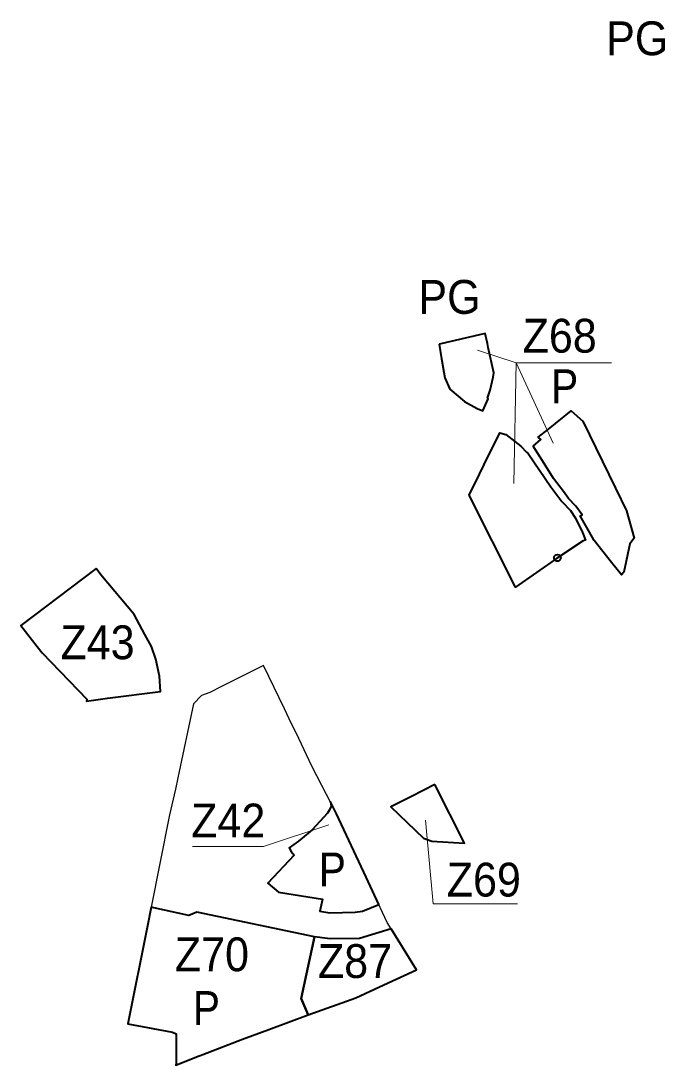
# Model space of a CAD drawing. Extents: x -650276 to -642489, y -1074425 to -1066658.
# Drawn here: x -647280 to -646824, y -1071533 to -1070793 of the extents above; entities that cross this region are included whole.
import ezdxf

# ---------------------------------------------------------------- set-up
doc = ezdxf.new("R2010")
doc.units = 0
doc.header["$LTSCALE"] = 9.6
doc.header["$PDMODE"] = 32
doc.header["$PDSIZE"] = 4.8
for name, color, linetype, lineweight in [('42', 7, 'Continuous', 25), ('44', 7, 'Continuous', 40), ('45', 7, 'Continuous', 40), ('46', 7, 'Continuous', 13), ('60', 7, 'Continuous', 35)]:
    doc.layers.add(name, color=color, linetype=linetype, lineweight=lineweight)

msp = doc.modelspace()

# ---------------------------------------------------------------- linework, layer by layer
at = {"layer": '42'}
msp.add_lwpolyline([(-647187.85, -1071421.58), (-647190.4, -1071434.75), (-647204.42, -1071504.1), (-647172.74, -1071510.15), (-647170.01, -1071511.22), (-647170.18, -1071532.22), (-647170.23, -1071533.44), (-647155.58, -1071527.62), (-647151.28, -1071525.99), (-647123.17, -1071515.01), (-647104.47, -1071508.08), (-647076.46, -1071497.69), (-647042.78, -1071485.76), (-647022.81, -1071476.61), (-646999.77, -1071465.81), (-647017.7, -1071436.79), (-647020.52, -1071432.42), (-647030.23, -1071411.53), (-647035.47, -1071400.31), (-647056.48, -1071355.32), (-647073.98, -1071321.53), (-647083.22, -1071302), (-647090, -1071287.89), (-647093.39, -1071280.83), (-647108.16, -1071250.08), (-647130.76, -1071261.49), (-647137.84, -1071265.06), (-647146.3, -1071269.33), (-647152.09, -1071271.47), (-647157.83, -1071277.35), (-647168.91, -1071329.88), (-647170.63, -1071337.91), (-647174.73, -1071356.1), (-647181.75, -1071390.51)], close=True, dxfattribs=at)
at = {"layer": '44'}
msp.add_line((-647081.488, -1071486.251), (-647076.46, -1071497.69), dxfattribs=at)
for points in [[(-647017.7, -1071436.79), (-647040.089, -1071443.76), (-647060.812, -1071444.006), (-647072.11, -1071442.6), (-647081.488, -1071486.251)], [(-647076.46, -1071497.69), (-647042.78, -1071485.76), (-647022.81, -1071476.61), (-646999.77, -1071465.81), (-647017.7, -1071436.79)]]:
    msp.add_lwpolyline(points, dxfattribs=at)
at = {"layer": '45'}
for points in [[(-646983.66, -1071022.3), (-646982.08, -1071032.76), (-646979.75, -1071046.19), (-646976.03, -1071054.29), (-646965.69, -1071063.05), (-646956.66, -1071067.91), (-646952.75, -1071069.62), (-646948.83, -1071061.12), (-646949.48, -1071060.79), (-646947.41, -1071054.95), (-646945.38, -1071045.82), (-646944.88, -1071042.78), (-646948.89, -1071024.84), (-646949.39, -1071021.83), (-646951.06, -1071014.78), (-646955.09, -1071015.67), (-646982.41, -1071022.23)], [(-646983.66, -1071022.3), (-646982.08, -1071032.76), (-646979.75, -1071046.19), (-646976.03, -1071054.29), (-646965.69, -1071063.05), (-646956.66, -1071067.91), (-646952.75, -1071069.62), (-646948.83, -1071061.12), (-646949.48, -1071060.79), (-646947.41, -1071054.95), (-646945.38, -1071045.82), (-646944.88, -1071042.78), (-646948.89, -1071024.84), (-646949.39, -1071021.83), (-646951.06, -1071014.78), (-646955.09, -1071015.67), (-646982.41, -1071022.23)], [(-646917.04, -1071094.75), (-646911.58, -1071089.9), (-646913.49, -1071088.22), (-646906.17, -1071082.72), (-646890.12, -1071069.67), (-646881.89, -1071077.03), (-646858.769, -1071124.46), (-646850.93, -1071140.54), (-646845.39, -1071159.98), (-646848.58, -1071163.95), (-646852.86, -1071183.98), (-646854.49, -1071185.87), (-646861.58, -1071177.05), (-646873.89, -1071161.58), (-646877.226, -1071155.611), (-646883.63, -1071144.15), (-646882.37, -1071143.39), (-646886.78, -1071137.25), (-646892.11, -1071131.81), (-646895.56, -1071126.84), (-646902.62, -1071117.58), (-646910.53, -1071105.18)], [(-646917.04, -1071094.75), (-646911.58, -1071089.9), (-646913.49, -1071088.22), (-646906.17, -1071082.72), (-646890.12, -1071069.67), (-646881.89, -1071077.03), (-646858.769, -1071124.46), (-646850.93, -1071140.54), (-646845.39, -1071159.98), (-646848.58, -1071163.95), (-646852.86, -1071183.98), (-646854.49, -1071185.87), (-646861.58, -1071177.05), (-646873.89, -1071161.58), (-646877.226, -1071155.611), (-646883.63, -1071144.15), (-646882.37, -1071143.39), (-646886.78, -1071137.25), (-646892.11, -1071131.81), (-646895.56, -1071126.84), (-646902.62, -1071117.58), (-646910.53, -1071105.18)], [(-646921.668, -1071098.861), (-646920.54, -1071099.98), (-646904.64, -1071123.54), (-646896.62, -1071133.93), (-646890.59, -1071140.39), (-646887.07, -1071145.66), (-646881.97, -1071155.84), (-646879.91, -1071161.24), (-646881.68, -1071161.83), (-646899.85, -1071173.89), (-646929.64, -1071194.58), (-646962.471, -1071129.325), (-646955.138, -1071114.466), (-646951.831, -1071107.765), (-646951.831, -1071107.765), (-646940.67, -1071085.15), (-646940.67, -1071085.15), (-646936.51, -1071086.33), (-646925.88, -1071094.68)], [(-647226.895, -1071181.511), (-647280.14, -1071221.92), (-647268.52, -1071236.78), (-647265.15, -1071241.1), (-647233.34, -1071274.07), (-647233.64, -1071275.42), (-647218.75, -1071273.32), (-647181.12, -1071268.66), (-647181.99, -1071257.66), (-647184.58, -1071245.67), (-647187.68, -1071236.74), (-647192.29, -1071228.1), (-647199.82, -1071213.98), (-647223.46, -1071185.83)], [(-647226.895, -1071181.511), (-647280.14, -1071221.92), (-647268.52, -1071236.78), (-647265.15, -1071241.1), (-647233.34, -1071274.07), (-647233.64, -1071275.42), (-647218.75, -1071273.32), (-647181.12, -1071268.66), (-647181.99, -1071257.66), (-647184.58, -1071245.67), (-647187.68, -1071236.74), (-647192.29, -1071228.1), (-647199.82, -1071213.98), (-647223.46, -1071185.83)], [(-646986.69, -1071334.53), (-647003.37, -1071342.99), (-647017.93, -1071350.33), (-646994.85, -1071372.49), (-646988.77, -1071374.77), (-646965.74, -1071376.18)], [(-646986.69, -1071334.53), (-647003.37, -1071342.99), (-647017.93, -1071350.33), (-646994.85, -1071372.49), (-646988.77, -1071374.77), (-646965.74, -1071376.18)], [(-647056.48, -1071355.32), (-647060.6, -1071346.87), (-647060.22, -1071349.87), (-647061.4, -1071352.51), (-647062.78, -1071354.77), (-647073.68, -1071366.75), (-647075.25, -1071368.01), (-647083.48, -1071374.62), (-647090.04, -1071379.44), (-647088.57, -1071381.97), (-647086.45, -1071384.59), (-647105.2, -1071404.54), (-647097.5, -1071410.96), (-647066.35, -1071415.79), (-647068.162, -1071424.298), (-647061.23, -1071425.434), (-647043.137, -1071424.978), (-647038.119, -1071424.37), (-647026.472, -1071419.614), (-647035.47, -1071400.31)], [(-647056.48, -1071355.32), (-647060.6, -1071346.87), (-647060.22, -1071349.87), (-647061.4, -1071352.51), (-647062.78, -1071354.77), (-647073.68, -1071366.75), (-647075.25, -1071368.01), (-647083.48, -1071374.62), (-647090.04, -1071379.44), (-647088.57, -1071381.97), (-647086.45, -1071384.59), (-647105.2, -1071404.54), (-647097.5, -1071410.96), (-647066.35, -1071415.79), (-647068.162, -1071424.298), (-647061.23, -1071425.434), (-647043.137, -1071424.978), (-647038.119, -1071424.37), (-647026.472, -1071419.614), (-647035.47, -1071400.31)], [(-647072.11, -1071442.6), (-647155.36, -1071425), (-647161.2, -1071427.33), (-647185.99, -1071421.98), (-647187.85, -1071421.58), (-647190.4, -1071434.75), (-647204.42, -1071504.1), (-647172.74, -1071510.15), (-647170.01, -1071511.22), (-647170.18, -1071532.22), (-647170.23, -1071533.44), (-647155.58, -1071527.62), (-647151.28, -1071525.99), (-647123.17, -1071515.01), (-647104.47, -1071508.08), (-647076.46, -1071497.69), (-647081.488, -1071486.251)], [(-647072.11, -1071442.6), (-647155.36, -1071425), (-647161.2, -1071427.33), (-647185.99, -1071421.98), (-647187.85, -1071421.58), (-647190.4, -1071434.75), (-647204.42, -1071504.1), (-647172.74, -1071510.15), (-647170.01, -1071511.22), (-647170.18, -1071532.22), (-647170.23, -1071533.44), (-647155.58, -1071527.62), (-647151.28, -1071525.99), (-647123.17, -1071515.01), (-647104.47, -1071508.08), (-647076.46, -1071497.69), (-647081.488, -1071486.251)]]:
    msp.add_lwpolyline(points, close=True, dxfattribs=at)
msp.add_point((-646899.85, -1071173.89), dxfattribs=at)
at = {"layer": '46'}
for q in [(-646956.598, -1071026.547), (-646902.758, -1071092.681)]:
    msp.add_line((-646929.085, -1071035.693), q, dxfattribs=at)
for points in [[(-646861.529, -1071035.693), (-646929.085, -1071035.693), (-646930.672, -1071121.165)], [(-646928.092, -1071419.173), (-646987.822, -1071419.173), (-646993.397, -1071359.705)], [(-646928.092, -1071419.173), (-646987.822, -1071419.173), (-646993.397, -1071359.705)], [(-647158.414, -1071378.568), (-647108.186, -1071378.568), (-647061.975, -1071363.219)], [(-647158.414, -1071378.568), (-647108.186, -1071378.568), (-647061.975, -1071363.219)]]:
    msp.add_lwpolyline(points, dxfattribs=at)

# ---------------------------------------------------------------- texts
at = {"layer": '44', "width": 0.95}
msp.add_text('Z87', height=24, dxfattribs=at).set_placement((-647069.618, -1071471.685))
msp.add_text('Z87', height=24, dxfattribs=at).set_placement((-647069.618, -1071471.685))
at = {"layer": '46', "width": 0.95}
for s, p in [('Z68', (-646924.523, -1071028.411)), ('Z43', (-647252.085, -1071245.723)), ('Z43', (-647252.085, -1071245.723)), ('Z42', (-647159.441, -1071372.08)), ('Z42', (-647159.441, -1071372.08)), ('Z69', (-646978.284, -1071413.97)), ('Z69', (-646978.284, -1071413.97)), ('Z70', (-647171.004, -1071466.914)), ('Z70', (-647171.004, -1071466.914))]:
    msp.add_text(s, height=24, dxfattribs=at).set_placement(p)
at = {"layer": '60'}
for s, width, p in [('PG', 0.95, (-646865.3, -1070817.6)), ('PG', 0.95, (-646998.384, -1071000.904)), ('P', 0.9, (-646904.37, -1071064.222)), ('P', 0.9, (-647069.021, -1071406.74)), ('P', 0.9, (-647069.021, -1071406.74)), ('P', 0.9, (-647158.268, -1071504.971)), ('P', 0.9, (-647158.268, -1071504.971))]:
    msp.add_text(s, height=24, dxfattribs=dict(at, width=width)).set_placement(p)

doc.saveas('drawing.dxf')
